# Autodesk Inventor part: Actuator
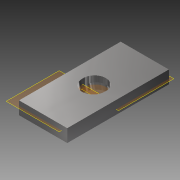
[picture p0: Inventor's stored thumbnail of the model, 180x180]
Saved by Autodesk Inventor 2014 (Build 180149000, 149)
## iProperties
Created: 2009-03
Part Number: Actuator
Document SubType Name: Modeling
Designer: tangg
Density: 7.84 g/cm^3
Material: Steel, High Strength Low Alloy
Mass: 5.99349 g
Surface Area: 9.85126 cm^2
Volume: 0.764475 cm^3
Appearance: Steel - Polished
Author: tangg
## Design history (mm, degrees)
sketch "Sketch1"
  geometry: L1 (-7.5, 15.631)-(7.5, 15.631); L2 (7.5, 15.631)-(7.5, -6); L3 (-5.189, -18.689)-(-5.163, -18.689); L4 (-7.5, -6)-(-7.5, 15.631); L5 (7.5, -6)-(7.5, -6); L6 (7.5, -6)-(7.5, -16); L7 (7.5, -16)-(-7.5, -16); L8 (-7.5, -16)-(-7.5, -6); L9 (-7.5, -6)-(-7.5, -6); C1 r 3.513 at (0, 0); 4 further points
  constraints: 18 end point, 4 perpendicular, 3 parallel, 2 horizontal alignment, 2 midpoint, 2 point on line, 2 vertical alignment, 1 centre point, 1 coincident, 1 horizontal
  dimensions: "d0" = 7.025 diameter of C1; "d3" = 15 distance between parallel lines of L4 L2; "d4" = 16 distance from line of point (0, 0) L7; "d5" = 15 distance between parallel lines of L8 L6; "d6" = 6 vertical distance of point (0, 0) L4.start
extrude "Extrusion1" new body sketch "Sketch1" stored distance "d1" = 4; taper "d2" = 0 deg
split "Split1"
sketch "Sketch4"
  geometry: L1 (7.5, 15.631)-(7.5, -16) reference; L2 (-7.5, 15.631)-(7.5, 15.631) reference; L3 (-7.5, -16)-(-7.5, 15.631) reference; L4 (-5, -8.5)-(-7.5, -6) reference; L5 (7.5, -16)-(-7.5, -16) reference; L6 (7.5, -6)-(5, -8.5) reference; L7 (-10.5, 0)-(10.5, 0) reference; C1 r 3.513 at (0, 0) reference; 2 other entities
  constraints: 2 other
split "Split2"
sketch "Sketch5"
  geometry: L1 (3.513, -2)-(0, -2) reference; L2 (-16, -2)-(15.631, -2) reference; L3 (-4.407, -2)-(-9.701, -2); A1 r 7.708 centre (-7.054, -9.24) between (-4.407, -2) and (-9.701, -2); 1 further point
  constraints: 2 end point, 2 point on circle, 2 point on line, 1 centre point, 1 collinear
extrude "Extrusion2" cut sketch "Sketch5" stored distance "d10" = 10; taper "d11" = 0 deg
workplane "Work Plane2"
  workplane "Work Plane1"
split "Split3"
split "Split4"
workplane "Work Plane3"
split "Split5"
chamfer "Chamfer1" distance "d15" = 0.2; stored, may be unused: second distance "d16" = 2, angle "d17" = 45 deg
chamfer "Chamfer2" distance "d18" = 0.2; stored, may be unused: second distance "d19" = 2, angle "d20" = 45 deg
sketch "Sketch6"
  geometry: L1 (0, 0)-(-3.661, 0); L2 (-6.012, 34.097)-(12.662, -71.809) reference; L3 (12.877, -52.874)-(3.918, -2.063) reference; L4 (4.046, -2.791)-(2.828, 4.116); L5 (4.046, -2.791)-(0.599, -3.399); L6 (2.828, 4.116)-(-0.619, 3.508)
  constraints: 12 end point, 3 point on line, 2 perpendicular, 1 collinear, 1 horizontal, 6 other
revolve "Revolution1" sketch "Sketch6" stored, may be unused: angle "d21" = 90 deg
body "Solid1"
other parameters: "d12" = -2.5, "d13" = 90 deg, "d14" = -1.5
